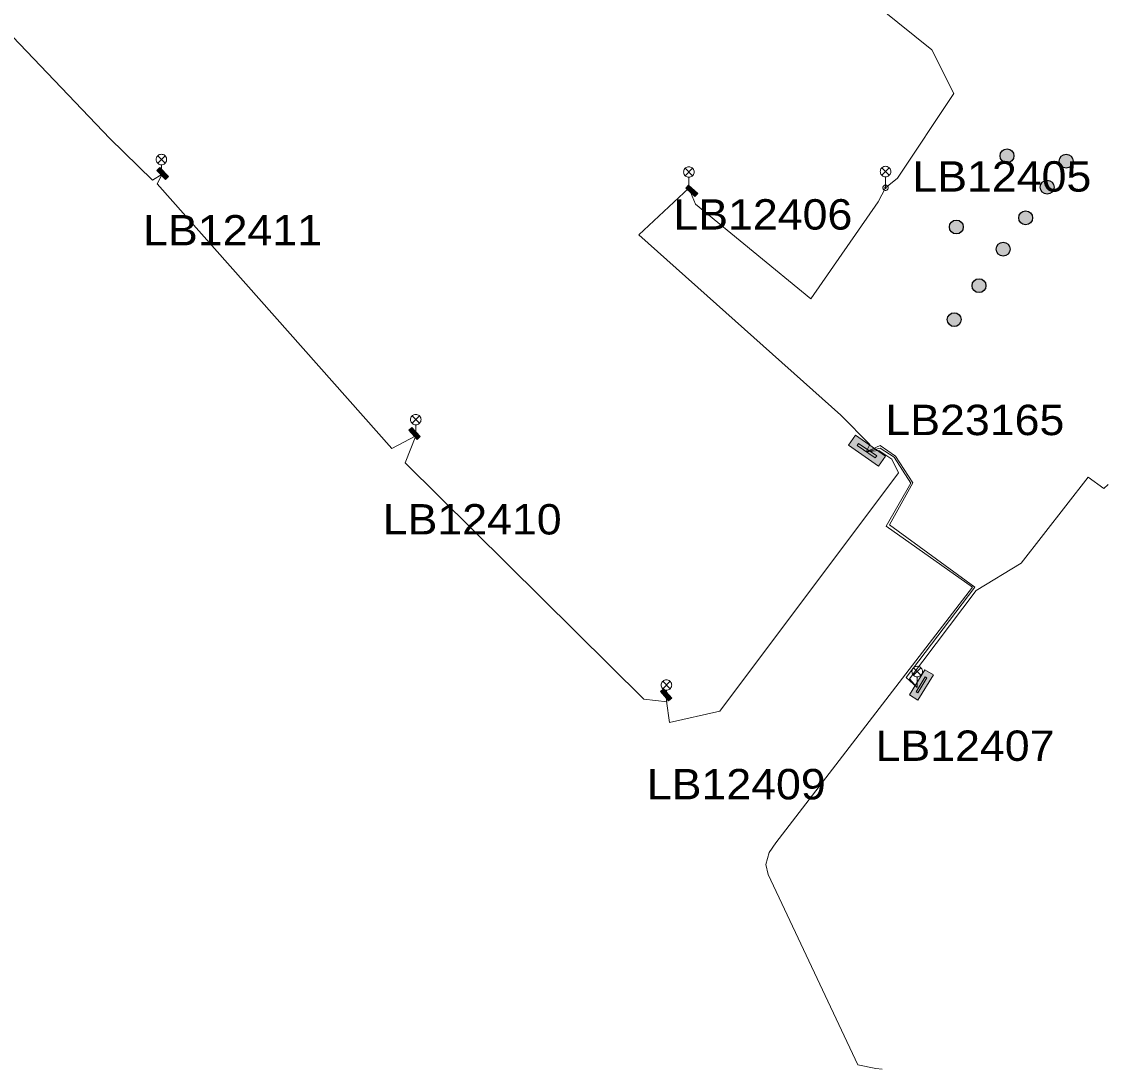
# Model space of a CAD drawing. Extents: x -688091 to -687952, y -973692 to -973558.
# Drawn here: x -688029.8 to -687952.3, y -973692 to -973617.3 of the extents above; entities that cross this region are included whole.
import ezdxf

# ---------------------------------------------------------------- set-up
doc = ezdxf.new("R2010")
doc.units = 0
doc.header["$LTSCALE"] = 0.87
doc.layers.add('1', color=7, linetype='Continuous', lineweight=13)

msp = doc.modelspace()

# ---------------------------------------------------------------- hatches: boundary and pattern name
at = {"layer": '1'}
for points in [[(-687959.3508, -973627.3497, 1), (-687959.6497, -973626.4055, 1)], [(-687955.1306, -973627.7277, 1), (-687955.4295, -973626.7835, 1)], [(-688019.548, -973628.561), (-688020.156, -973627.917), (-688019.942, -973627.714), (-688019.333, -973628.358)], [(-688019.584, -973628.351), (-688019.949, -973627.965), (-688019.906, -973627.924), (-688019.541, -973628.311)], [(-687956.4856, -973629.5796, 1), (-687956.7844, -973628.6354, 1)], [(-687981.768, -973629.788), (-687982.424, -973629.192), (-687982.225, -973628.973), (-687981.569, -973629.569)], [(-687981.82, -973629.581), (-687982.213, -973629.224), (-687982.173, -973629.18), (-687981.78, -973629.537)], [(-687958.0227, -973631.7706, 1), (-687958.3216, -973630.8264, 1)], [(-687962.9694, -973632.4211, 1), (-687963.2683, -973631.4769, 1)], [(-687959.6258, -973634.0089, 1), (-687959.9246, -973633.0647, 1)], [(-687961.3499, -973636.6091, 1), (-687961.6488, -973635.6649, 1)], [(-687963.1162, -973639.0289, 1), (-687963.4151, -973638.0847, 1)], [(-688001.577, -973647.098), (-688002.173, -973646.443), (-688001.954, -973646.244), (-688001.358, -973646.9)], [(-688001.577, -973647.098), (-688002.173, -973646.443), (-688001.954, -973646.244), (-688001.358, -973646.9)], [(-688001.577, -973647.098), (-688002.173, -973646.443), (-688001.954, -973646.244), (-688001.358, -973646.9)], [(-688001.608, -973646.888), (-688001.966, -973646.494), (-688001.922, -973646.455), (-688001.565, -973646.848)], [(-688001.608, -973646.888), (-688001.966, -973646.494), (-688001.922, -973646.455), (-688001.565, -973646.848)], [(-688001.608, -973646.888), (-688001.966, -973646.494), (-688001.922, -973646.455), (-688001.565, -973646.848)], [(-687968.669, -973649.011), (-687970.822, -973647.51), (-687970.322, -973646.792), (-687968.169, -973648.294)], [(-687968.9, -973648.424), (-687970.192, -973647.523), (-687970.092, -973647.38), (-687968.799, -973648.28)], [(-687966.452, -973665.32), (-687965.355, -973663.529), (-687964.758, -973663.894), (-687965.855, -973665.685)], [(-687965.994, -973665.108), (-687965.336, -973664.033), (-687965.216, -973664.106), (-687965.874, -973665.181)], [(-687983.642, -973665.752), (-687984.226, -973665.086), (-687984.004, -973664.891), (-687983.42, -973665.558)], [(-687983.67, -973665.541), (-687984.02, -973665.141), (-687983.976, -973665.102), (-687983.626, -973665.502)]]:
    msp.add_hatch(color=256, dxfattribs=at).paths.add_polyline_path(points)

# ---------------------------------------------------------------- linework, layer by layer
for p, q in [((-688020.094, -973626.874), (-688019.564, -973627.404)), ((-688020.094, -973627.404), (-688019.564, -973626.874)), ((-688019.829, -973628.289), (-688019.829, -973627.514)), ((-687982.465, -973627.765), (-687981.935, -973628.295)), ((-687982.465, -973628.295), (-687981.935, -973627.765)), ((-687982.465, -973627.765), (-687981.935, -973628.295)), ((-687982.465, -973628.295), (-687981.935, -973627.765)), ((-687968.435, -973627.735), (-687967.905, -973628.265)), ((-687968.435, -973628.265), (-687967.905, -973627.735)), ((-687968.435, -973627.735), (-687967.905, -973628.265)), ((-687968.435, -973628.265), (-687967.905, -973627.735)), ((-687968.435, -973627.735), (-687967.905, -973628.265)), ((-687968.435, -973628.265), (-687967.905, -973627.735)), ((-687982.2, -973629.18), (-687982.2, -973628.405)), ((-687982.2, -973629.18), (-687982.2, -973628.405)), ((-687968.17, -973629.15), (-687968.17, -973628.375)), ((-687968.17, -973629.15), (-687968.17, -973628.375)), ((-687968.17, -973629.15), (-687968.17, -973628.375)), ((-688001.947, -973645.422), (-688001.417, -973645.952)), ((-688001.947, -973645.952), (-688001.417, -973645.422)), ((-688001.947, -973645.422), (-688001.417, -973645.952)), ((-688001.947, -973645.952), (-688001.417, -973645.422)), ((-688001.947, -973645.422), (-688001.417, -973645.952)), ((-688001.947, -973645.952), (-688001.417, -973645.422)), ((-688001.682, -973646.837), (-688001.682, -973646.062)), ((-688001.682, -973646.837), (-688001.682, -973646.062)), ((-688001.682, -973646.837), (-688001.682, -973646.062)), ((-687966.174, -973663.385), (-687965.644, -973663.915)), ((-687966.174, -973663.915), (-687965.644, -973663.385)), ((-687984.065, -973664.349), (-687983.535, -973664.879)), ((-687984.065, -973664.879), (-687983.535, -973664.349)), ((-687965.909, -973664.8), (-687965.909, -973664.025)), ((-687983.8, -973665.764), (-687983.8, -973664.989))]:
    msp.add_line(p, q, dxfattribs=at)
for points in [[(-687968.17, -973629.15), (-687967.313, -973628.479), (-687963.291, -973622.435), (-687964.867, -973619.32), (-687975.911, -973610.419), (-687976.73, -973610.89)], [(-688030.924, -973617.509), (-688030.924, -973617.873), (-688023.518, -973625.63), (-688020.453, -973628.618), (-688019.78, -973628.172)], [(-688019.78, -973628.172), (-688020.142, -973628.865), (-688003.386, -973647.747), (-688001.682, -973646.837)], [(-687969.545, -973647.974), (-687969.284, -973647.467), (-687971.347, -973645.364), (-687985.77, -973632.51), (-687982.2, -973629.18)], [(-687982.2, -973629.18), (-687981.714, -973630.331), (-687973.49, -973637.082), (-687968.687, -973630.146), (-687968.17, -973629.15)], [(-688001.682, -973646.837), (-688002.432, -973648.77), (-687985.421, -973665.613), (-687983.755, -973665.816)], [(-687983.8, -973665.764), (-687983.589, -973667.288), (-687979.993, -973666.487), (-687967.24, -973649.492), (-687967.725, -973648.507), (-687968.637, -973647.901), (-687969.545, -973647.974)], [(-687968.416, -973692.014), (-687968.852, -973691.968), (-687970.146, -973691.708), (-687976.55, -973678.132), (-687976.71, -973677.42), (-687976.46, -973676.56), (-687976, -973675.86), (-687961.97, -973657.632), (-687968.114, -973653.291), (-687966.367, -973650.207), (-687967.544, -973648.357), (-687968.552, -973647.714), (-687969.545, -973647.974)], [(-687965.909, -973664.8), (-687966.701, -973664.086), (-687961.804, -973657.639), (-687967.891, -973653.194), (-687966.227, -973650.184), (-687967.466, -973648.301), (-687968.554, -973647.532), (-687969.545, -973647.974)], [(-687952.278, -973650.304), (-687952.602, -973650.609), (-687953.712, -973649.802), (-687958.495, -973655.933), (-687961.699, -973657.877), (-687966.462, -973664.174), (-687965.909, -973664.8)]]:
    msp.add_lwpolyline(points, dxfattribs=at)
for points in [[(-688019.454, -973627.139), (-688019.46, -973627.074), (-688019.477, -973627.011), (-688019.504, -973626.952), (-688019.542, -973626.898), (-688019.588, -973626.852), (-688019.642, -973626.814), (-688019.701, -973626.787), (-688019.764, -973626.77), (-688019.829, -973626.764), (-688019.894, -973626.77), (-688019.957, -973626.787), (-688020.016, -973626.814), (-688020.07, -973626.852), (-688020.116, -973626.898), (-688020.154, -973626.952), (-688020.181, -973627.011), (-688020.198, -973627.074), (-688020.204, -973627.139), (-688020.198, -973627.204), (-688020.181, -973627.267), (-688020.154, -973627.327), (-688020.116, -973627.38), (-688020.07, -973627.426), (-688020.016, -973627.464), (-688019.957, -973627.491), (-688019.894, -973627.508), (-688019.829, -973627.514), (-688019.764, -973627.508), (-688019.701, -973627.491), (-688019.642, -973627.464), (-688019.588, -973627.426), (-688019.542, -973627.38), (-688019.504, -973627.327), (-688019.477, -973627.267), (-688019.46, -973627.204)], [(-688019.548, -973628.561), (-688020.156, -973627.917), (-688019.942, -973627.714), (-688019.333, -973628.358)], [(-688019.548, -973628.561), (-688020.156, -973627.917), (-688019.942, -973627.714), (-688019.333, -973628.358)], [(-688019.584, -973628.351), (-688019.949, -973627.965), (-688019.906, -973627.924), (-688019.541, -973628.311)], [(-687981.825, -973628.03), (-687981.831, -973627.965), (-687981.848, -973627.902), (-687981.875, -973627.842), (-687981.913, -973627.789), (-687981.959, -973627.743), (-687982.013, -973627.705), (-687982.072, -973627.678), (-687982.135, -973627.661), (-687982.2, -973627.655), (-687982.265, -973627.661), (-687982.328, -973627.678), (-687982.388, -973627.705), (-687982.441, -973627.743), (-687982.487, -973627.789), (-687982.525, -973627.842), (-687982.552, -973627.902), (-687982.569, -973627.965), (-687982.575, -973628.03), (-687982.569, -973628.095), (-687982.552, -973628.158), (-687982.525, -973628.218), (-687982.487, -973628.271), (-687982.441, -973628.317), (-687982.388, -973628.355), (-687982.328, -973628.382), (-687982.265, -973628.399), (-687982.2, -973628.405), (-687982.135, -973628.399), (-687982.072, -973628.382), (-687982.013, -973628.355), (-687981.959, -973628.317), (-687981.913, -973628.271), (-687981.875, -973628.218), (-687981.848, -973628.158), (-687981.831, -973628.095)], [(-687981.825, -973628.03), (-687981.831, -973627.965), (-687981.848, -973627.902), (-687981.875, -973627.842), (-687981.913, -973627.789), (-687981.959, -973627.743), (-687982.013, -973627.705), (-687982.072, -973627.678), (-687982.135, -973627.661), (-687982.2, -973627.655), (-687982.265, -973627.661), (-687982.328, -973627.678), (-687982.388, -973627.705), (-687982.441, -973627.743), (-687982.487, -973627.789), (-687982.525, -973627.842), (-687982.552, -973627.902), (-687982.569, -973627.965), (-687982.575, -973628.03), (-687982.569, -973628.095), (-687982.552, -973628.158), (-687982.525, -973628.218), (-687982.487, -973628.271), (-687982.441, -973628.317), (-687982.388, -973628.355), (-687982.328, -973628.382), (-687982.265, -973628.399), (-687982.2, -973628.405), (-687982.135, -973628.399), (-687982.072, -973628.382), (-687982.013, -973628.355), (-687981.959, -973628.317), (-687981.913, -973628.271), (-687981.875, -973628.218), (-687981.848, -973628.158), (-687981.831, -973628.095)], [(-687967.795, -973628), (-687967.801, -973627.935), (-687967.818, -973627.872), (-687967.845, -973627.812), (-687967.883, -973627.759), (-687967.929, -973627.713), (-687967.982, -973627.675), (-687968.042, -973627.648), (-687968.105, -973627.631), (-687968.17, -973627.625), (-687968.235, -973627.631), (-687968.298, -973627.648), (-687968.358, -973627.675), (-687968.411, -973627.713), (-687968.457, -973627.759), (-687968.495, -973627.812), (-687968.522, -973627.872), (-687968.539, -973627.935), (-687968.545, -973628), (-687968.539, -973628.065), (-687968.522, -973628.128), (-687968.495, -973628.188), (-687968.457, -973628.241), (-687968.411, -973628.287), (-687968.358, -973628.325), (-687968.298, -973628.352), (-687968.235, -973628.369), (-687968.17, -973628.375), (-687968.105, -973628.369), (-687968.042, -973628.352), (-687967.982, -973628.325), (-687967.929, -973628.287), (-687967.883, -973628.241), (-687967.845, -973628.188), (-687967.818, -973628.128), (-687967.801, -973628.065)], [(-687967.795, -973628), (-687967.801, -973627.935), (-687967.818, -973627.872), (-687967.845, -973627.812), (-687967.883, -973627.759), (-687967.929, -973627.713), (-687967.982, -973627.675), (-687968.042, -973627.648), (-687968.105, -973627.631), (-687968.17, -973627.625), (-687968.235, -973627.631), (-687968.298, -973627.648), (-687968.358, -973627.675), (-687968.411, -973627.713), (-687968.457, -973627.759), (-687968.495, -973627.812), (-687968.522, -973627.872), (-687968.539, -973627.935), (-687968.545, -973628), (-687968.539, -973628.065), (-687968.522, -973628.128), (-687968.495, -973628.188), (-687968.457, -973628.241), (-687968.411, -973628.287), (-687968.358, -973628.325), (-687968.298, -973628.352), (-687968.235, -973628.369), (-687968.17, -973628.375), (-687968.105, -973628.369), (-687968.042, -973628.352), (-687967.982, -973628.325), (-687967.929, -973628.287), (-687967.883, -973628.241), (-687967.845, -973628.188), (-687967.818, -973628.128), (-687967.801, -973628.065)], [(-687967.795, -973628), (-687967.801, -973627.935), (-687967.818, -973627.872), (-687967.845, -973627.812), (-687967.883, -973627.759), (-687967.929, -973627.713), (-687967.982, -973627.675), (-687968.042, -973627.648), (-687968.105, -973627.631), (-687968.17, -973627.625), (-687968.235, -973627.631), (-687968.298, -973627.648), (-687968.358, -973627.675), (-687968.411, -973627.713), (-687968.457, -973627.759), (-687968.495, -973627.812), (-687968.522, -973627.872), (-687968.539, -973627.935), (-687968.545, -973628), (-687968.539, -973628.065), (-687968.522, -973628.128), (-687968.495, -973628.188), (-687968.457, -973628.241), (-687968.411, -973628.287), (-687968.358, -973628.325), (-687968.298, -973628.352), (-687968.235, -973628.369), (-687968.17, -973628.375), (-687968.105, -973628.369), (-687968.042, -973628.352), (-687967.982, -973628.325), (-687967.929, -973628.287), (-687967.883, -973628.241), (-687967.845, -973628.188), (-687967.818, -973628.128), (-687967.801, -973628.065)], [(-687981.768, -973629.788), (-687982.424, -973629.192), (-687982.225, -973628.973), (-687981.569, -973629.569)], [(-687981.768, -973629.788), (-687982.424, -973629.192), (-687982.225, -973628.973), (-687981.569, -973629.569)], [(-687981.82, -973629.581), (-687982.213, -973629.224), (-687982.173, -973629.18), (-687981.78, -973629.537)], [(-687967.98, -973629.15), (-687967.983, -973629.117), (-687967.991, -973629.085), (-687968.005, -973629.055), (-687968.024, -973629.028), (-687968.048, -973629.004), (-687968.075, -973628.985), (-687968.105, -973628.971), (-687968.137, -973628.963), (-687968.17, -973628.96), (-687968.203, -973628.963), (-687968.235, -973628.971), (-687968.265, -973628.985), (-687968.292, -973629.004), (-687968.316, -973629.028), (-687968.335, -973629.055), (-687968.349, -973629.085), (-687968.357, -973629.117), (-687968.36, -973629.15), (-687968.357, -973629.183), (-687968.349, -973629.215), (-687968.335, -973629.245), (-687968.316, -973629.272), (-687968.292, -973629.296), (-687968.265, -973629.315), (-687968.235, -973629.329), (-687968.203, -973629.337), (-687968.17, -973629.34), (-687968.137, -973629.337), (-687968.105, -973629.329), (-687968.075, -973629.315), (-687968.048, -973629.296), (-687968.024, -973629.272), (-687968.005, -973629.245), (-687967.991, -973629.215), (-687967.983, -973629.183)], [(-687967.98, -973629.15), (-687967.983, -973629.117), (-687967.991, -973629.085), (-687968.005, -973629.055), (-687968.024, -973629.028), (-687968.048, -973629.004), (-687968.075, -973628.985), (-687968.105, -973628.971), (-687968.137, -973628.963), (-687968.17, -973628.96), (-687968.203, -973628.963), (-687968.235, -973628.971), (-687968.265, -973628.985), (-687968.292, -973629.004), (-687968.316, -973629.028), (-687968.335, -973629.055), (-687968.349, -973629.085), (-687968.357, -973629.117), (-687968.36, -973629.15), (-687968.357, -973629.183), (-687968.349, -973629.215), (-687968.335, -973629.245), (-687968.316, -973629.272), (-687968.292, -973629.296), (-687968.265, -973629.315), (-687968.235, -973629.329), (-687968.203, -973629.337), (-687968.17, -973629.34), (-687968.137, -973629.337), (-687968.105, -973629.329), (-687968.075, -973629.315), (-687968.048, -973629.296), (-687968.024, -973629.272), (-687968.005, -973629.245), (-687967.991, -973629.215), (-687967.983, -973629.183)], [(-687967.98, -973629.15), (-687967.983, -973629.117), (-687967.991, -973629.085), (-687968.005, -973629.055), (-687968.024, -973629.028), (-687968.048, -973629.004), (-687968.075, -973628.985), (-687968.105, -973628.971), (-687968.137, -973628.963), (-687968.17, -973628.96), (-687968.203, -973628.963), (-687968.235, -973628.971), (-687968.265, -973628.985), (-687968.292, -973629.004), (-687968.316, -973629.028), (-687968.335, -973629.055), (-687968.349, -973629.085), (-687968.357, -973629.117), (-687968.36, -973629.15), (-687968.357, -973629.183), (-687968.349, -973629.215), (-687968.335, -973629.245), (-687968.316, -973629.272), (-687968.292, -973629.296), (-687968.265, -973629.315), (-687968.235, -973629.329), (-687968.203, -973629.337), (-687968.17, -973629.34), (-687968.137, -973629.337), (-687968.105, -973629.329), (-687968.075, -973629.315), (-687968.048, -973629.296), (-687968.024, -973629.272), (-687968.005, -973629.245), (-687967.991, -973629.215), (-687967.983, -973629.183)], [(-687968.12, -973629.15), (-687968.121, -973629.141), (-687968.123, -973629.133), (-687968.127, -973629.125), (-687968.132, -973629.118), (-687968.138, -973629.112), (-687968.145, -973629.107), (-687968.153, -973629.103), (-687968.161, -973629.101), (-687968.17, -973629.1), (-687968.179, -973629.101), (-687968.187, -973629.103), (-687968.195, -973629.107), (-687968.202, -973629.112), (-687968.208, -973629.118), (-687968.213, -973629.125), (-687968.217, -973629.133), (-687968.219, -973629.141), (-687968.22, -973629.15), (-687968.219, -973629.159), (-687968.217, -973629.167), (-687968.213, -973629.175), (-687968.208, -973629.182), (-687968.202, -973629.188), (-687968.195, -973629.193), (-687968.187, -973629.197), (-687968.179, -973629.199), (-687968.17, -973629.2), (-687968.161, -973629.199), (-687968.153, -973629.197), (-687968.145, -973629.193), (-687968.138, -973629.188), (-687968.132, -973629.182), (-687968.127, -973629.175), (-687968.123, -973629.167), (-687968.121, -973629.159)], [(-687968.12, -973629.15), (-687968.121, -973629.141), (-687968.123, -973629.133), (-687968.127, -973629.125), (-687968.132, -973629.118), (-687968.138, -973629.112), (-687968.145, -973629.107), (-687968.153, -973629.103), (-687968.161, -973629.101), (-687968.17, -973629.1), (-687968.179, -973629.101), (-687968.187, -973629.103), (-687968.195, -973629.107), (-687968.202, -973629.112), (-687968.208, -973629.118), (-687968.213, -973629.125), (-687968.217, -973629.133), (-687968.219, -973629.141), (-687968.22, -973629.15), (-687968.219, -973629.159), (-687968.217, -973629.167), (-687968.213, -973629.175), (-687968.208, -973629.182), (-687968.202, -973629.188), (-687968.195, -973629.193), (-687968.187, -973629.197), (-687968.179, -973629.199), (-687968.17, -973629.2), (-687968.161, -973629.199), (-687968.153, -973629.197), (-687968.145, -973629.193), (-687968.138, -973629.188), (-687968.132, -973629.182), (-687968.127, -973629.175), (-687968.123, -973629.167), (-687968.121, -973629.159)], [(-687968.12, -973629.15), (-687968.121, -973629.141), (-687968.123, -973629.133), (-687968.127, -973629.125), (-687968.132, -973629.118), (-687968.138, -973629.112), (-687968.145, -973629.107), (-687968.153, -973629.103), (-687968.161, -973629.101), (-687968.17, -973629.1), (-687968.179, -973629.101), (-687968.187, -973629.103), (-687968.195, -973629.107), (-687968.202, -973629.112), (-687968.208, -973629.118), (-687968.213, -973629.125), (-687968.217, -973629.133), (-687968.219, -973629.141), (-687968.22, -973629.15), (-687968.219, -973629.159), (-687968.217, -973629.167), (-687968.213, -973629.175), (-687968.208, -973629.182), (-687968.202, -973629.188), (-687968.195, -973629.193), (-687968.187, -973629.197), (-687968.179, -973629.199), (-687968.17, -973629.2), (-687968.161, -973629.199), (-687968.153, -973629.197), (-687968.145, -973629.193), (-687968.138, -973629.188), (-687968.132, -973629.182), (-687968.127, -973629.175), (-687968.123, -973629.167), (-687968.121, -973629.159)], [(-688001.307, -973645.687), (-688001.313, -973645.622), (-688001.33, -973645.559), (-688001.357, -973645.5), (-688001.395, -973645.446), (-688001.441, -973645.4), (-688001.494, -973645.362), (-688001.554, -973645.335), (-688001.617, -973645.318), (-688001.682, -973645.312), (-688001.747, -973645.318), (-688001.81, -973645.335), (-688001.87, -973645.362), (-688001.923, -973645.4), (-688001.969, -973645.446), (-688002.007, -973645.5), (-688002.034, -973645.559), (-688002.051, -973645.622), (-688002.057, -973645.687), (-688002.051, -973645.752), (-688002.034, -973645.815), (-688002.007, -973645.874), (-688001.969, -973645.928), (-688001.923, -973645.974), (-688001.87, -973646.012), (-688001.81, -973646.039), (-688001.747, -973646.056), (-688001.682, -973646.062), (-688001.617, -973646.056), (-688001.554, -973646.039), (-688001.494, -973646.012), (-688001.441, -973645.974), (-688001.395, -973645.928), (-688001.357, -973645.874), (-688001.33, -973645.815), (-688001.313, -973645.752)], [(-688001.307, -973645.687), (-688001.313, -973645.622), (-688001.33, -973645.559), (-688001.357, -973645.5), (-688001.395, -973645.446), (-688001.441, -973645.4), (-688001.494, -973645.362), (-688001.554, -973645.335), (-688001.617, -973645.318), (-688001.682, -973645.312), (-688001.747, -973645.318), (-688001.81, -973645.335), (-688001.87, -973645.362), (-688001.923, -973645.4), (-688001.969, -973645.446), (-688002.007, -973645.5), (-688002.034, -973645.559), (-688002.051, -973645.622), (-688002.057, -973645.687), (-688002.051, -973645.752), (-688002.034, -973645.815), (-688002.007, -973645.874), (-688001.969, -973645.928), (-688001.923, -973645.974), (-688001.87, -973646.012), (-688001.81, -973646.039), (-688001.747, -973646.056), (-688001.682, -973646.062), (-688001.617, -973646.056), (-688001.554, -973646.039), (-688001.494, -973646.012), (-688001.441, -973645.974), (-688001.395, -973645.928), (-688001.357, -973645.874), (-688001.33, -973645.815), (-688001.313, -973645.752)], [(-688001.307, -973645.687), (-688001.313, -973645.622), (-688001.33, -973645.559), (-688001.357, -973645.5), (-688001.395, -973645.446), (-688001.441, -973645.4), (-688001.494, -973645.362), (-688001.554, -973645.335), (-688001.617, -973645.318), (-688001.682, -973645.312), (-688001.747, -973645.318), (-688001.81, -973645.335), (-688001.87, -973645.362), (-688001.923, -973645.4), (-688001.969, -973645.446), (-688002.007, -973645.5), (-688002.034, -973645.559), (-688002.051, -973645.622), (-688002.057, -973645.687), (-688002.051, -973645.752), (-688002.034, -973645.815), (-688002.007, -973645.874), (-688001.969, -973645.928), (-688001.923, -973645.974), (-688001.87, -973646.012), (-688001.81, -973646.039), (-688001.747, -973646.056), (-688001.682, -973646.062), (-688001.617, -973646.056), (-688001.554, -973646.039), (-688001.494, -973646.012), (-688001.441, -973645.974), (-688001.395, -973645.928), (-688001.357, -973645.874), (-688001.33, -973645.815), (-688001.313, -973645.752)], [(-688001.577, -973647.098), (-688002.173, -973646.443), (-688001.954, -973646.244), (-688001.358, -973646.9)], [(-688001.577, -973647.098), (-688002.173, -973646.443), (-688001.954, -973646.244), (-688001.358, -973646.9)], [(-688001.577, -973647.098), (-688002.173, -973646.443), (-688001.954, -973646.244), (-688001.358, -973646.9)], [(-688001.577, -973647.098), (-688002.173, -973646.443), (-688001.954, -973646.244), (-688001.358, -973646.9)], [(-688001.577, -973647.098), (-688002.173, -973646.443), (-688001.954, -973646.244), (-688001.358, -973646.9)], [(-688001.577, -973647.098), (-688002.173, -973646.443), (-688001.954, -973646.244), (-688001.358, -973646.9)], [(-688001.608, -973646.888), (-688001.966, -973646.494), (-688001.922, -973646.455), (-688001.565, -973646.848)], [(-688001.608, -973646.888), (-688001.966, -973646.494), (-688001.922, -973646.455), (-688001.565, -973646.848)], [(-688001.608, -973646.888), (-688001.966, -973646.494), (-688001.922, -973646.455), (-688001.565, -973646.848)], [(-687968.669, -973649.011), (-687970.822, -973647.51), (-687970.322, -973646.792), (-687968.169, -973648.294)], [(-687968.669, -973649.011), (-687970.822, -973647.51), (-687970.322, -973646.792), (-687968.169, -973648.294)], [(-687968.9, -973648.424), (-687970.192, -973647.523), (-687970.092, -973647.38), (-687968.799, -973648.28)], [(-687966.452, -973665.32), (-687965.355, -973663.529), (-687964.758, -973663.894), (-687965.855, -973665.685)], [(-687966.452, -973665.32), (-687965.355, -973663.529), (-687964.758, -973663.894), (-687965.855, -973665.685)], [(-687965.534, -973663.65), (-687965.54, -973663.585), (-687965.557, -973663.522), (-687965.584, -973663.462), (-687965.622, -973663.409), (-687965.668, -973663.363), (-687965.722, -973663.325), (-687965.781, -973663.298), (-687965.844, -973663.281), (-687965.909, -973663.275), (-687965.974, -973663.281), (-687966.037, -973663.298), (-687966.096, -973663.325), (-687966.15, -973663.363), (-687966.196, -973663.409), (-687966.234, -973663.462), (-687966.261, -973663.522), (-687966.278, -973663.585), (-687966.284, -973663.65), (-687966.278, -973663.715), (-687966.261, -973663.778), (-687966.234, -973663.838), (-687966.196, -973663.891), (-687966.15, -973663.937), (-687966.096, -973663.975), (-687966.037, -973664.002), (-687965.974, -973664.019), (-687965.909, -973664.025), (-687965.844, -973664.019), (-687965.781, -973664.002), (-687965.722, -973663.975), (-687965.668, -973663.937), (-687965.622, -973663.891), (-687965.584, -973663.838), (-687965.557, -973663.778), (-687965.54, -973663.715)], [(-687983.425, -973664.614), (-687983.431, -973664.549), (-687983.448, -973664.486), (-687983.475, -973664.426), (-687983.513, -973664.373), (-687983.559, -973664.327), (-687983.612, -973664.289), (-687983.672, -973664.262), (-687983.735, -973664.245), (-687983.8, -973664.239), (-687983.865, -973664.245), (-687983.928, -973664.262), (-687983.988, -973664.289), (-687984.041, -973664.327), (-687984.087, -973664.373), (-687984.125, -973664.426), (-687984.152, -973664.486), (-687984.169, -973664.549), (-687984.175, -973664.614), (-687984.169, -973664.679), (-687984.152, -973664.742), (-687984.125, -973664.802), (-687984.087, -973664.855), (-687984.041, -973664.901), (-687983.988, -973664.939), (-687983.928, -973664.966), (-687983.865, -973664.983), (-687983.8, -973664.989), (-687983.735, -973664.983), (-687983.672, -973664.966), (-687983.612, -973664.939), (-687983.559, -973664.901), (-687983.513, -973664.855), (-687983.475, -973664.802), (-687983.448, -973664.742), (-687983.431, -973664.679)], [(-687965.994, -973665.108), (-687965.336, -973664.033), (-687965.216, -973664.106), (-687965.874, -973665.181)], [(-687983.642, -973665.752), (-687984.226, -973665.086), (-687984.004, -973664.891), (-687983.42, -973665.558)], [(-687983.642, -973665.752), (-687984.226, -973665.086), (-687984.004, -973664.891), (-687983.42, -973665.558)], [(-687983.67, -973665.541), (-687984.02, -973665.141), (-687983.976, -973665.102), (-687983.626, -973665.502)]]:
    msp.add_lwpolyline(points, close=True, dxfattribs=at)
at = {"layer": '1', "lineweight": 25}
for centre in [(-687959.5003, -973626.8776), (-687955.28, -973627.2556), (-687956.635, -973629.1075), (-687958.1721, -973631.2985), (-687963.1188, -973631.949), (-687959.7752, -973633.5368), (-687961.4994, -973636.137), (-687963.2656, -973638.5568)]:
    msp.add_circle(centre, 0.4952, dxfattribs=at)

# ---------------------------------------------------------------- texts
at = {"layer": '1', "width": 1.1}
for s, height, p in [('LB12405', 2.167, (-687966.252, -973629.429)), ('LB12406', 2.167, (-687983.302, -973632.136)), ('LB12411', 2.167, (-688021.133, -973633.268)), ('LB23165', 2.168, (-687968.18, -973646.794)), ('LB12410', 2.167, (-688004.038, -973653.879)), ('LB12410', 2.167, (-688004.038, -973653.879)), ('LB12410', 2.167, (-688004.038, -973653.879)), ('LB12407', 2.167, (-687968.879, -973670.024)), ('LB12409', 2.167, (-687985.198, -973672.767))]:
    msp.add_text(s, height=height, dxfattribs=at).set_placement(p)

doc.saveas('drawing.dxf')
